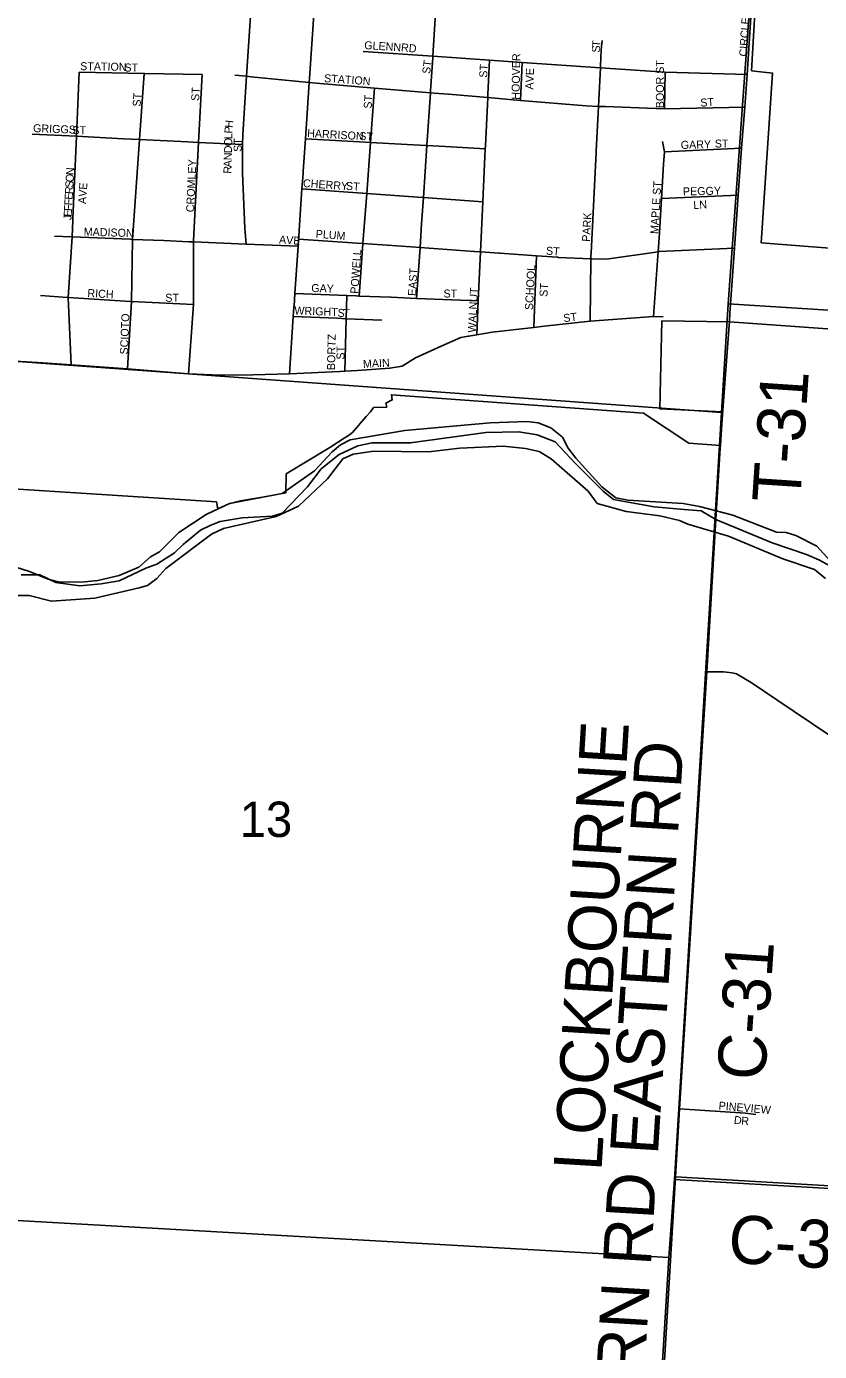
# Model space of a CAD drawing. Extents: x 1643459 to 2064572, y 425441 to 780708.
# Drawn here: x 1839200 to 1844154, y 618149 to 626429 of the extents above; entities that cross this region are included whole.
import ezdxf

# ---------------------------------------------------------------- set-up
doc = ezdxf.new("R2010")
doc.units = 0
for name, color, linetype in [('GM_X_Adjacent_County', 7, 'Continuous'), ('GM_X_Airport_Class_2', 7, 'Continuous'), ('GM_X_Airport_Class_3', 7, 'Continuous'), ('GM_X_City_Street', 7, 'Continuous'), ('GM_X_County', 7, 'Continuous'), ('GM_X_Major_River', 7, 'Continuous'), ('GM_X_Major_River_Text', 7, 'Continuous'), ('GM_X_Minor_Lake', 7, 'Continuous'), ('GM_X_Rail_Line_Text', 7, 'Continuous'), ('GM_X_Section_Text', 7, 'Continuous'), ('GM_X_State_Route', 7, 'Continuous'), ('GM_X_Township', 7, 'Continuous'), ('GM_X_Unincorporated_Text', 7, 'Continuous'), ('RD_X_Text', 7, 'Continuous')]:
    doc.layers.add(name, color=color, linetype=linetype)

msp = doc.modelspace()

# ---------------------------------------------------------------- linework, layer by layer
at = {"layer": 'GM_X_Airport_Class_2'}
for points in [[(1843589.1, 624562.2), (1843590.7, 624583.8), (1843594.7, 624637.1), (1843622.5, 625043.3), (1843646.8, 625374.1), (1843667.6, 625667.5), (1843686.7, 625924.4), (1843702.4, 626129.3), (1843820.4, 627990.4), (1843824.4, 628042.8)], [(1840571.5, 625069.1), (1840564.6, 625168.3), (1840549.1, 625511.7), (1840550.5, 625690.4), (1840551, 625754.7), (1840574.5, 626117.4), (1840598.8, 626493.2), (1840621.7, 626860.5)], [(1841737.6, 626233.4), (1841738.2, 626242.7), (1841758.3, 626544.4)], [(1841302.4, 626272.9), (1841738.2, 626242.7), (1842091.9, 626218.3), (1842295.6, 626204.2), (1842784.9, 626170.4), (1843189.4, 626142.4), (1843702.4, 626129.3)], [(1842785.5, 626182.5), (1842790.5, 626283.5), (1842797, 626341.6)], [(1841723.7, 626026), (1841737.6, 626233.4), (1841737.6, 626233.4)], [(1842082, 626003.8), (1842091.9, 626218.3)], [(1842286.7, 625967.4), (1842295.6, 626204.2)], [(1839489.6, 625229.4), (1839512.1, 625742.7), (1839529.7, 626143.9)], [(1839529.7, 626143.9), (1839935.2, 626135.5)], [(1839832.2, 624289.7), (1839856.3, 624709.6), (1839862.5, 625098.7), (1839906.2, 625722.9), (1839935.2, 626135.5)], [(1839935.2, 626135.5), (1839938.8, 626135.5), (1840296.8, 626128)], [(1840243.3, 625089.7), (1840274.9, 625704.3), (1840296.8, 626128)], [(1840501.9, 626124.4), (1840574.5, 626117.4), (1840603.7, 626114.5), (1840625.4, 626112.4)], [(1840625.4, 626112.4), (1840966.3, 626079), (1841010.6, 626074.7), (1841032.7, 626072.5)], [(1842774.9, 625969.9), (1842784.9, 626170.4), (1842785.5, 626181.3), (1842785.5, 626182.5)], [(1843185.1, 625914.8), (1843189.4, 626142.4)], [(1841032.7, 626072.5), (1841081.8, 626067.7), (1841374.1, 626043.7), (1841723, 626015), (1841746.5, 626013.1)], [(1841277.9, 624744.4), (1841302.3, 625072.5), (1841325.4, 625384.7), (1841349, 625703.6), (1841374.1, 626043.7)], [(1841668.4, 625196.6), (1841679.3, 625359.5), (1841701, 625684.4), (1841723, 626015), (1841723.7, 626026), (1841723.7, 626026)], [(1841746.5, 626013.1), (1841836.5, 626005.7), (1842081.1, 625984.9), (1842286.7, 625967.4), (1842695.4, 625932.8), (1842772.9, 625929.9), (1842797.6, 625929), (1842817.4, 625928.3)], [(1842067.1, 625682.1), (1842067.1, 625682.1), (1842081.1, 625984.9), (1842082, 626003.8), (1842082, 626003.8)], [(1842759, 625651), (1842772.9, 625929.9), (1842774.7, 625966.1), (1842774.9, 625969.9)], [(1842817.4, 625928.3), (1843185.1, 625914.8), (1843686.7, 625924.4)], [(1839235.4, 625756.6), (1839512.1, 625742.7), (1839807.2, 625727.8)], [(1839807.2, 625727.8), (1839807.2, 625727.8), (1839906.2, 625722.9), (1840207.4, 625707.7), (1840207.5, 625707.7)], [(1840207.5, 625707.7), (1840274.9, 625704.3), (1840550.5, 625690.4)], [(1840942.3, 625725.9), (1841317, 625705.4)], [(1841317, 625705.4), (1841318.7, 625705.3), (1841349, 625703.6), (1841691.7, 625684.9)], [(1843180.4, 625568.1), (1843185, 625644.9), (1843173.7, 625710.2)], [(1841691.7, 625684.9), (1841692.5, 625684.9), (1841701, 625684.4), (1841852.2, 625676.1)], [(1841852.2, 625676.1), (1841852.7, 625676.1), (1842066.3, 625664.4)], [(1842012.7, 624502.5), (1842022.5, 624714.6), (1842036.6, 625020.6), (1842051, 625333.1), (1842066.3, 625664.4), (1842067.1, 625682.1)], [(1842727.2, 625013.3), (1842758.7, 625643.4), (1842759, 625651)], [(1843185, 625644.9), (1843667.6, 625667.5)], [(1843163.2, 625282.3), (1843167.6, 625353.2), (1843180.4, 625568.1)], [(1840921.2, 625413.4), (1841297.8, 625386.6)], [(1841297.8, 625386.6), (1841299.1, 625386.5), (1841325.4, 625384.7), (1841674.4, 625359.9)], [(1843167.6, 625353.2), (1843646.8, 625374.1)], [(1841674.4, 625359.9), (1841675.1, 625359.8), (1841679.3, 625359.5), (1842051, 625333.1)], [(1843154.2, 625139.4), (1843163.2, 625282.3)], [(1839479.9, 624315.5), (1839460.1, 624735.5), (1839484.6, 625114.5), (1839489, 625216.3), (1839489.6, 625229.4)], [(1841637.3, 624730), (1841658.5, 625047.3), (1841668.4, 625196.6), (1841668.4, 625196.6)], [(1839375.2, 625119.1), (1839480.1, 625114.7)], [(1839480.1, 625114.7), (1839480.2, 625114.7), (1839484.6, 625114.5), (1839847.4, 625099.3)], [(1843145, 624996.5), (1843146.8, 625021.7), (1843154.2, 625139.4)], [(1839847.4, 625099.3), (1839847.8, 625099.3), (1839862.5, 625098.7), (1840057.3, 625090.6)], [(1840057.3, 625090.6), (1840057.9, 625090.5), (1840214.7, 625084)], [(1840211.8, 624259.2), (1840244, 624691.9), (1840242.7, 625078.5), (1840242.9, 625082.8), (1840243.3, 625089.7)], [(1840214.7, 625084), (1840215.4, 625084), (1840242.9, 625082.8), (1840571.5, 625069.1), (1840896.8, 625055.4)], [(1840899.9, 625100.8), (1841266.5, 625075), (1841266.6, 625075)], [(1841266.6, 625075), (1841302.3, 625072.5), (1841422.9, 625064), (1841423.8, 625063.9)], [(1841423.8, 625063.9), (1841631.5, 625049.2), (1841633.3, 625049.1)], [(1841633.3, 625049.1), (1841658.5, 625047.3), (1841996.6, 625023.5), (1842000, 625023.2)], [(1843150.3, 625021.8), (1843622.5, 625043.3)], [(1842000, 625023.2), (1842036.6, 625020.6), (1842153, 625012.4), (1842157.2, 625012.1)], [(1842157.2, 625012.1), (1842387.1, 624995.9), (1842518.1, 624986.7), (1842523.3, 624986.3), (1842523.9, 624986.3)], [(1842370.2, 624548.3), (1842387.1, 624995.9)], [(1842523.9, 624986.3), (1842725.4, 624977.9), (1842733.8, 624977.6)], [(1842721.5, 624587.6), (1842725.4, 624977.9), (1842726.5, 624997.9), (1842727.2, 625013.3)], [(1842733.8, 624977.6), (1842822.5, 624973.9), (1843146.8, 625021.7), (1843150.3, 625021.8)], [(1843117.3, 624615.6), (1843145, 624996.5)], [(1839286.9, 624748.2), (1839455.6, 624735.9)], [(1839455.6, 624735.9), (1839460.1, 624735.5), (1839849.6, 624710)], [(1839849.6, 624710), (1839856.3, 624709.6), (1840244, 624691.9)], [(1840876.8, 624760.4), (1841201.9, 624747.4), (1841258.7, 624745.2)], [(1841188.5, 624275.3), (1841197.8, 624603), (1841201.9, 624747.4)], [(1841258.7, 624745.2), (1841259.3, 624745.1), (1841277.9, 624744.4), (1841476.9, 624736.4)], [(1841476.9, 624736.4), (1841477.3, 624736.4), (1841637.3, 624730), (1842022.5, 624714.6)], [(1840867.1, 624616.9), (1841143.4, 624605.2)], [(1841964.3, 624494), (1842012.7, 624502.5), (1842110, 624519.6), (1842370.2, 624548.3), (1842433.6, 624555.2), (1842721.5, 624587.6), (1843117.3, 624615.6), (1843176.3, 624615.4)], [(1841143.4, 624605.2), (1841143.8, 624605.2), (1841197.8, 624603), (1841419.8, 624593.6)], [(1841160.4, 624273.9), (1841188.5, 624275.3), (1841268.7, 624279.1), (1841469.6, 624293.6), (1841546, 624307.1), (1841630.8, 624358.7), (1841790, 624431.7), (1841912.9, 624485), (1841959.6, 624493.2), (1841964.3, 624494)], [(1840842.7, 624258.6), (1841158.3, 624273.8), (1841160.4, 624273.9)]]:
    msp.add_lwpolyline(points, dxfattribs=at)
at = {"layer": 'GM_X_City_Street'}
for points in [[(1844223.1, 623056.3), (1844149.6, 623096), (1844072.1, 623129.8), (1843857.5, 623203.3), (1843505.9, 623348.2), (1843414.4, 623402), (1843309, 623410), (1843120.3, 623427.8), (1842959.3, 623455.7), (1842867.9, 623473.5), (1842802.4, 623525.2), (1842629.5, 623698.1), (1842502.3, 623833.2), (1842391, 623876.9), (1842275.8, 623896.8), (1842069.1, 623892.8), (1841599.6, 623826.9), (1841358.8, 623827.9), (1841270.4, 623808.2), (1841153.8, 623754.5), (1841041, 623664.7), (1840956.3, 623552.7), (1840797, 623386.8), (1840736.7, 623369), (1840548.1, 623357.8), (1840409.5, 623336.3), (1840351.2, 623312.5), (1840286.9, 623280.7), (1840178.1, 623192.8), (1840125.7, 623138.9), (1840015, 623069.1), (1839946.7, 623043.3), (1839778.5, 622964.1), (1839666.9, 622946.7), (1839534.3, 622932.7), (1839384.3, 622953.7), (1839283.1, 623002.5), (1839167.9, 623002.5)], [(1839167.9, 623002.5), (1839283.1, 623002.5), (1839384.3, 622953.7), (1839534.3, 622932.7), (1839666.9, 622946.7), (1839778.5, 622964.1), (1839946.7, 623043.3), (1840015, 623069.1), (1840125.7, 623138.9), (1840178.1, 623192.8), (1840286.9, 623280.7), (1840351.2, 623312.5), (1840409.5, 623336.3), (1840548.1, 623357.8), (1840736.7, 623369), (1840797, 623386.8), (1840956.3, 623552.7), (1841041, 623664.7), (1841153.8, 623754.5), (1841270.4, 623808.2), (1841358.8, 623827.9), (1841599.6, 623826.9), (1842069.1, 623892.8), (1842275.8, 623896.8), (1842391, 623876.9), (1842502.3, 623833.2), (1842629.5, 623698.1), (1842802.4, 623525.2), (1842867.9, 623473.5), (1842959.3, 623455.7), (1843120.3, 623427.8), (1843309, 623410), (1843414.4, 623402), (1843505.9, 623348.2), (1843857.5, 623203.3), (1844072.1, 623129.8), (1844149.6, 623096), (1844223.1, 623056.3)]]:
    msp.add_lwpolyline(points, dxfattribs=at)
at = {"layer": 'GM_X_County'}
msp.add_lwpolyline([(1843279.9, 619665.2), (1843690.8, 619637.4), (1843756.5, 619629.4)], dxfattribs=at)
at = {"layer": 'GM_X_Major_River_Text'}
for points in [[(1843545.6, 623974.4), (1843549.2, 624031.3), (1843589.1, 624562.2)], [(1843532.1, 623760.5), (1843535.8, 623818.3), (1843545.6, 623974.4)], [(1843501.5, 623279.2), (1843505.9, 623348.2), (1843532.1, 623760.5)], [(1847205.1, 621488.7), (1847199.8, 621490.7), (1847032.1, 621553.8), (1846865.5, 621647.7), (1846731, 621715.6), (1846590.6, 621747.4), (1846412.2, 621761), (1846216.2, 621775.6), (1845981.8, 621748.4), (1845682, 621732), (1845518.4, 621775.6), (1845338.5, 621824.7), (1845075.4, 621849.2), (1844410.4, 621890.2), (1844327.9, 621924.2), (1844218.9, 621999.2), (1843887.3, 622222.1), (1843727.2, 622329.1), (1843635.2, 622383), (1843609.3, 622389.8), (1843554.8, 622395.9), (1843449.8, 622396.6)], [(1841145.1, 613509.1), (1842773.6, 613408.9), (1842843.5, 613401.1), (1842877.6, 613404.2), (1842899.4, 613419.7), (1842911.8, 613457), (1842922.6, 613703.9), (1843253.5, 619240.3)]]:
    msp.add_lwpolyline(points, dxfattribs=at)
at = {"layer": 'GM_X_Minor_Lake'}
for points in [[(1843253.5, 619240.3), (1843279.9, 619665.2), (1843449.8, 622396.6), (1843501.5, 623279.2)], [(1843253.5, 619240.3), (1844648.3, 619158.7), (1845426.3, 619114.9), (1849830.4, 618825.4)]]:
    msp.add_lwpolyline(points, dxfattribs=at)
at = {"layer": 'GM_X_Rail_Line_Text'}
for points in [[(1843835.2, 627991.7), (1843729.5, 626152.5), (1843860.9, 626137.9), (1843790.2, 625077.3), (1845020.3, 624980.5)], [(1844816.3, 624496), (1843590.7, 624583.7), (1843169.6, 624588.8), (1843156.7, 624038.9), (1843548.6, 624021.8), (1843535.3, 623810.5), (1843337.9, 623826.1), (1843053.6, 624012.2), (1841479.3, 624127.3), (1841485.2, 624095.2), (1841445, 624075.2), (1841451, 624051.1), (1841368.7, 624047.3), (1841348.5, 624021.3), (1841322.4, 623991.2), (1841235.8, 623891.1), (1841211.6, 623873.1), (1841185.5, 623857.1), (1841095, 623797.2), (1840821.6, 623633.3), (1840819.7, 623514.2), (1840731.3, 623497.5), (1840663, 623485.8), (1840612.8, 623477.9), (1840536.5, 623464.2), (1840464.2, 623446.5), (1840395.3, 623415), (1840387.7, 623457.9), (1838300.1, 623590.9)]]:
    msp.add_lwpolyline(points, dxfattribs=at)
at = {"layer": 'GM_X_State_Route'}
for points in [[(1843965.1, 630055.8), (1847786.3, 629841.4), (1847476.4, 624450.7), (1843583.4, 624695.4), (1843917.7, 629340)], [(1838557.1, 629689.7), (1843917.7, 629340), (1843583.4, 624695.4), (1843542.1, 624017.5), (1838195.8, 624403.2)], [(1843583.4, 624695.4), (1847476.4, 624450.7), (1847128.2, 618998.1), (1843247.1, 619224.7), (1843542.1, 624017.5)], [(1843542.1, 624017.5), (1843247.1, 619224.7), (1843212.7, 618736.9), (1837858, 619040.6), (1838195.8, 624403.2)], [(1843247.1, 619224.7), (1847128.2, 618998.1), (1846855.6, 613483), (1842906.5, 613710.2), (1843212.7, 618736.9)], [(1843212.7, 618736.9), (1842906.5, 613710.2), (1842889.1, 613414.2), (1837502.5, 613740.2), (1837858, 619040.6)]]:
    msp.add_lwpolyline(points, close=True, dxfattribs=at)
at = {"layer": 'GM_X_Unincorporated_Text'}
for points in [[(1842097.5, 623952.4), (1842326.3, 623961.4), (1842396.5, 623953.1), (1842474.6, 623920.6), (1842548.6, 623862.1), (1842584.4, 623793.7), (1842632.3, 623731.3), (1842794, 623552), (1842882, 623483.3), (1842956.2, 623469), (1843303.2, 623447.4), (1843403.5, 623428.9), (1843612, 623375.8), (1843884.4, 623268.2), (1843946.6, 623266), (1844006.7, 623247.6), (1844136.8, 623180.8), (1844260.7, 623045.8)], [(1840797.2, 623510.5), (1840998.5, 623652.1), (1841109.4, 623770), (1841161.8, 623814), (1841222.1, 623845.8), (1841563.5, 623904.5), (1842097.5, 623952.4)], [(1841711.4, 623771.4), (1841908.2, 623794.7), (1842179.1, 623805.5), (1842317.5, 623790.9), (1842401.7, 623772.4), (1842477.7, 623727.9), (1842709.6, 623524.2), (1842765.5, 623447.7), (1842945.8, 623398.8), (1843156.4, 623371.8), (1843278.7, 623341.1), (1843330.8, 623318.8), (1843585.3, 623243.5), (1843925.8, 623101.5), (1844122.1, 623036.4), (1844192.1, 622979.9)], [(1840760.5, 623366.2), (1840899.2, 623431.8), (1841080.6, 623601.6), (1841175.4, 623727.6), (1841241.8, 623757.4), (1841370.3, 623774.9), (1841711.4, 623771.4)], [(1839093.6, 623062.3), (1839219.9, 623023.7), (1839336, 622975), (1839408.2, 622956.6), (1839562.7, 622958), (1839645, 622967.6), (1839779.6, 622997.2), (1839902.2, 623050.8), (1839974.8, 623114.7), (1840031.1, 623146.6), (1840152, 623266.5), (1840323.1, 623380.1), (1840467.9, 623447.7), (1840797.2, 623510.5)], [(1839074.7, 622873.8), (1839217.2, 622873.2), (1839355.5, 622838.4), (1839626.5, 622857.3), (1839903.7, 622920.3), (1839955.9, 622936.2), (1840014.3, 622980.1), (1840070.8, 623042), (1840356.6, 623255.5), (1840431, 623291.3), (1840760.5, 623366.2)]]:
    msp.add_lwpolyline(points, dxfattribs=at)
at = {"layer": 'RD_X_Text'}
for points in [[(1840968, 626104.1), (1841028.8, 626998.8), (1841030.4, 627022.4), (1841033.6, 627053.1)], [(1840928.7, 625524.1), (1840942.3, 625725.9), (1840966.3, 626079), (1840966.7, 626083.8), (1840968, 626104.1)], [(1840903.6, 625155), (1840921.2, 625413.4), (1840927.7, 625510.2), (1840928.7, 625524.1)], [(1840871.4, 624680.5), (1840876.8, 624760.4), (1840896.8, 625055.4), (1840899.9, 625100.8), (1840902.9, 625145.1), (1840903.6, 625155)], [(1840842.7, 624258.6), (1840867.1, 624616.9), (1840871.1, 624675.8), (1840871.4, 624680.5)], [(1838994.1, 624346.1), (1839063.3, 624341.2), (1839302.2, 624326.5)], [(1839302.2, 624326.5), (1839479.9, 624315.5), (1839832.2, 624289.7), (1840211.8, 624259.2), (1840409.6, 624249.5), (1840613.9, 624252.8), (1840842.7, 624258.6)]]:
    msp.add_lwpolyline(points, dxfattribs=at)

# ---------------------------------------------------------------- texts
at = {"layer": 'GM_X_Adjacent_County'}
msp.add_text('13', height=221, rotation=0.00001, dxfattribs=at).set_placement((1840531.6, 621364.3))
at = {"layer": 'GM_X_Airport_Class_3'}
for s, rotation, p in [('CIRCLEVILLE', 86.14516, (1843701.3, 626239.8)), ('GLENN', 356.34522, (1841308.8, 626288.1)), ('RD', 353.99459, (1841538, 626274.9)), ('S', 87.43092, (1842781.6, 626264.9)), ('T', 85.51539, (1842783.2, 626299.7)), ('STATION', 359.02578, (1839535.2, 626156.2)), ('ST', 0.00001, (1839812.2, 626147.4)), ('ST', 82.87834, (1841721.3, 626130.3)), ('ST', 86.4126, (1842077.6, 626107.7)), ('HOOVER', 89.01275, (1842280, 625970.9)), ('BOOR ST', 90, (1843182, 625917.9)), ('STATION', 356.12348, (1841058.1, 626081.3)), ('AVE', 88.02609, (1842366, 626034.1)), ('ST', 86.42535, (1840278.1, 625962.5)), ('ST', 86.42621, (1839912.9, 625927.3)), ('ST', 86.42535, (1841356.1, 625914.1)), ('ST', 3.57463, (1843410.8, 625927.3)), ('GRIGGS', 357.79869, (1839240.6, 625769)), ('ST', 0.00001, (1839486.6, 625755.7)), ('P', 86.69288, (1840486.2, 625758.9)), ('H', 84.28505, (1840488.2, 625793.5)), ('HARRISON', 356.77431, (1840952.4, 625738.1)), ('O', 88.67533, (1840484.4, 625680.2)), ('L', 88.67675, (1840485.4, 625724.2)), ('ST', 90, (1840544.4, 625645.1)), ('ST', 356.42537, (1841278, 625720.5)), ('GARY', 1.47368, (1843288, 625663.4)), ('ST', 0.00001, (1843499.4, 625672.2)), ('N', 88.67533, (1840482.4, 625592.2)), ('D', 88.67533, (1840483.4, 625636.2)), ('N', 86.80682, (1839496.5, 625498.8)), ('CROMLEY', 87.47529, (1840247.2, 625267.2)), ('R', 88.66438, (1840480.4, 625508.6)), ('A', 88.67533, (1840481.3, 625548.2)), ('S', 86.83574, (1839492.1, 625419.8)), ('O', 86.829, (1839494, 625454.9)), ('AVE', 86.05688, (1839571.9, 625318.7)), ('CHERRY', 355.91272, (1840926.1, 625425.7)), ('ST', 356.42622, (1841194.4, 625408.1)), ('MAPLE ST', 86.5802, (1843146.8, 625130.8)), ('E', 86.80198, (1839487.9, 625345)), ('R', 86.82021, (1839489.9, 625380.2)), ('PEGGY', 1.24464, (1843301.2, 625373)), ('E', 86.99295, (1839482.2, 625239.6)), ('F', 86.82925, (1839484, 625274.8)), ('F', 86.82164, (1839486, 625309.9)), ('LN', 3.01098, (1843367, 625288)), ('J', 88.51326, (1839481.6, 625218)), ('PARK', 86.90163, (1842720, 625082.5)), ('MADISON', 358.23518, (1839557.3, 625122.2)), ('AVE', 355.9166, (1840776.5, 625073.7)), ('PLUM', 355.60387, (1841005.4, 625108.9)), ('POWELL', 85.91271, (1841272.4, 624757)), ('ST', 356.42537, (1842444, 625003.4)), ('EAST', 86.73128, (1841633.2, 624743.7)), ('SCHOOL', 86.93517, (1842363.6, 624655.7)), ('RICH', 356.53377, (1839579.6, 624739.3)), ('GAY', 358.09182, (1840978.5, 624770.1)), ('ST', 0.00001, (1841805.4, 624735)), ('WALNUT', 87.13559, (1842007.2, 624514.8)), ('ST', 86.42535, (1842453.9, 624738.4)), ('ST', 0.00001, (1840067.4, 624708.6)), ('SCIOTO', 87.7106, (1839833.6, 624378.3)), ('WRIGHT', 357.95181, (1840873, 624629.4)), ('S', 355.84432, (1841141.8, 624616.1)), ('T', 357.289, (1841178.3, 624613.5)), ('ST', 7.12165, (1842556.7, 624580.9)), ('BORTZ', 88.75525, (1841127.2, 624281.1)), ('ST', 90, (1841186.8, 624347.2)), ('MAIN', 3.09247, (1841303.3, 624295))]:
    msp.add_text(s, height=50, rotation=rotation, dxfattribs=at).set_placement(p)
at = {"layer": 'GM_X_Major_River'}
for s, rotation, p in [('T-31', 86.1639, (1844032.2, 623446.9)), ('LOCKBOURNE EASTERN RD', 86.61833, (1842809.5, 613763.3))]:
    msp.add_text(s, height=300, rotation=rotation, dxfattribs=at).set_placement(p)
at = {"layer": 'GM_X_Section_Text'}
for s, rotation, p in [('LOCKBOURNE', 86.4739, (1842791.6, 619272.3)), ('EASTERN RD', 86.41692, (1843144.3, 619373.7)), ('C-31', 86.2096, (1843812.7, 619837.9)), ('C-32', 356.57378, (1843578.3, 618705.3))]:
    msp.add_text(s, height=300, rotation=rotation, dxfattribs=at).set_placement(p)
at = {"layer": 'GM_X_Township'}
for s, rotation, p in [('PINEVIEW', 354.8822, (1843522, 619661.7)), ('D', 352.15117, (1843616.4, 619573)), ('R', 355.92744, (1843663.5, 619566.6))]:
    msp.add_text(s, height=50, rotation=rotation, dxfattribs=at).set_placement(p)

doc.saveas('drawing.dxf')
